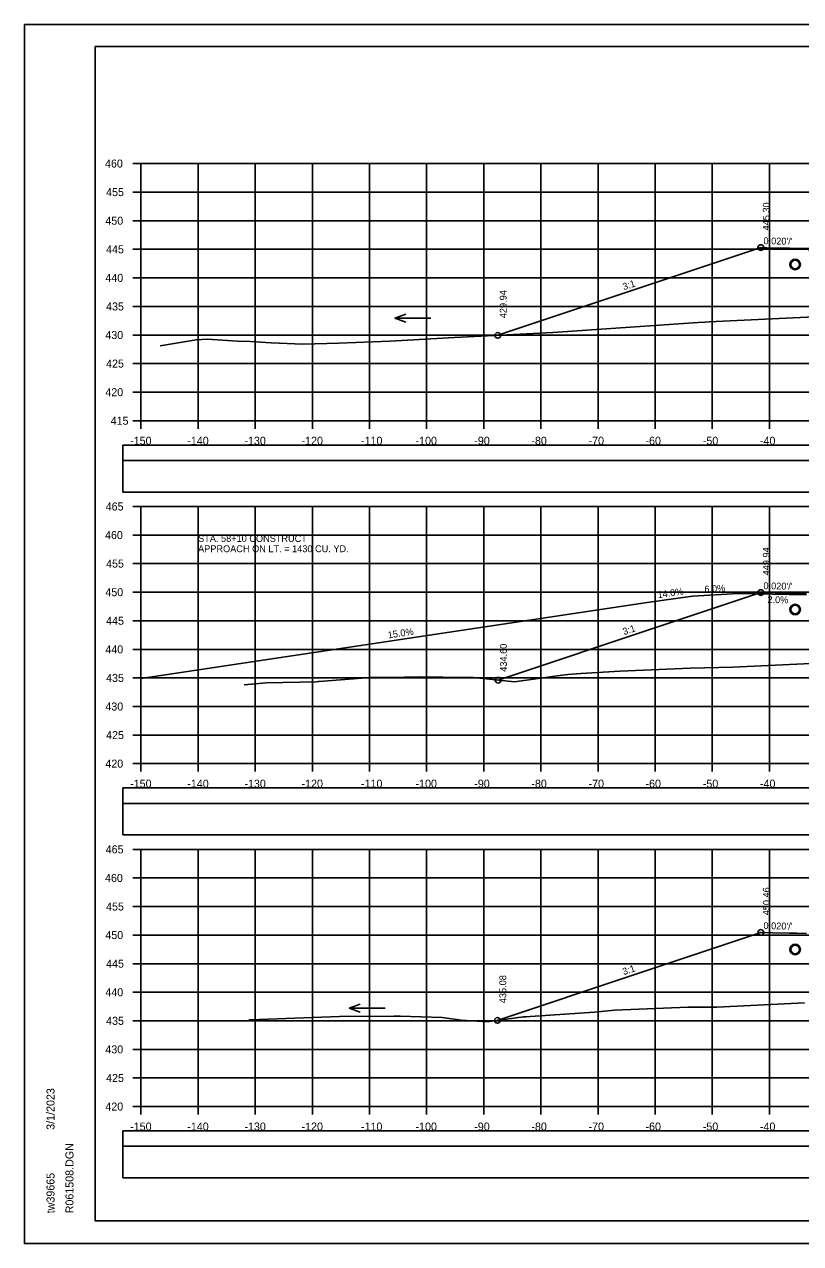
# Model space of a CAD drawing. Extents: x 1371057 to 1372761, y 380005 to 390517.
# Drawn here: x 1371390.5 to 1371526.3, y 384271.8 to 384485.2 of the extents above; entities that cross this region are included whole.
import ezdxf

# ---------------------------------------------------------------- set-up
doc = ezdxf.new("R2010")
doc.units = 0
for name, color, linetype in [('R_Axis', 7, 'Continuous'), ('R_Axis Annot', 7, 'Continuous'), ('R_Border', 7, 'Continuous'), ('R_Detour', 7, 'Continuous'), ('R_Dimension', 7, 'Continuous'), ('R_Drive', 7, 'Continuous'), ('R_Exist Surface', 7, 'Continuous'), ('R_Fin Surface', 7, 'Continuous'), ('R_Grid', 7, 'Continuous'), ('R_No Plot', 7, 'Continuous'), ('R_Water', 7, 'Continuous'), ('R_Water Annot', 7, 'Continuous'), ('R_Xsect Elev', 7, 'Continuous'), ('R_Xsect Slope', 7, 'Continuous')]:
    doc.layers.add(name, color=color, linetype=linetype)

msp = doc.modelspace()

# ---------------------------------------------------------------- linework, layer by layer
at = {"layer": 'R_Axis'}
for p, q in [((1371409.47, 384460.82), (1371410.87, 384460.82)), ((1371410.87, 384415.82), (1371410.87, 384460.82)), ((1371409.47, 384455.82), (1371410.87, 384455.82)), ((1371409.47, 384450.82), (1371410.87, 384450.82)), ((1371409.47, 384445.82), (1371410.87, 384445.82)), ((1371409.47, 384440.82), (1371410.87, 384440.82)), ((1371409.47, 384435.82), (1371410.87, 384435.82)), ((1371409.47, 384430.82), (1371410.87, 384430.82)), ((1371409.47, 384425.82), (1371410.87, 384425.82)), ((1371409.47, 384420.82), (1371410.87, 384420.82)), ((1371409.47, 384415.82), (1371410.87, 384415.82)), ((1371410.87, 384415.82), (1371710.87, 384415.82)), ((1371410.87, 384414.42), (1371410.87, 384415.82)), ((1371420.87, 384414.42), (1371420.87, 384415.82)), ((1371430.87, 384414.42), (1371430.87, 384415.82)), ((1371440.87, 384414.42), (1371440.87, 384415.82)), ((1371450.87, 384414.42), (1371450.87, 384415.82)), ((1371460.87, 384414.42), (1371460.87, 384415.82)), ((1371470.87, 384414.42), (1371470.87, 384415.82)), ((1371480.87, 384414.42), (1371480.87, 384415.82)), ((1371490.87, 384414.42), (1371490.87, 384415.82)), ((1371500.87, 384414.42), (1371500.87, 384415.82)), ((1371510.87, 384414.42), (1371510.87, 384415.82)), ((1371520.87, 384414.42), (1371520.87, 384415.82)), ((1371409.47, 384400.82), (1371410.87, 384400.82)), ((1371410.87, 384355.82), (1371410.87, 384400.82)), ((1371409.47, 384395.82), (1371410.87, 384395.82)), ((1371409.47, 384390.82), (1371410.87, 384390.82)), ((1371409.47, 384385.82), (1371410.87, 384385.82)), ((1371409.47, 384380.82), (1371410.87, 384380.82)), ((1371409.47, 384375.82), (1371410.87, 384375.82)), ((1371409.47, 384370.82), (1371410.87, 384370.82)), ((1371409.47, 384365.82), (1371410.87, 384365.82)), ((1371409.47, 384360.82), (1371410.87, 384360.82)), ((1371409.47, 384355.82), (1371410.87, 384355.82)), ((1371410.87, 384355.82), (1371710.87, 384355.82)), ((1371410.87, 384354.42), (1371410.87, 384355.82)), ((1371420.87, 384354.42), (1371420.87, 384355.82)), ((1371430.87, 384354.42), (1371430.87, 384355.82)), ((1371440.87, 384354.42), (1371440.87, 384355.82)), ((1371450.87, 384354.42), (1371450.87, 384355.82)), ((1371460.87, 384354.42), (1371460.87, 384355.82)), ((1371470.87, 384354.42), (1371470.87, 384355.82)), ((1371480.87, 384354.42), (1371480.87, 384355.82)), ((1371490.87, 384354.42), (1371490.87, 384355.82)), ((1371500.87, 384354.42), (1371500.87, 384355.82)), ((1371510.87, 384354.42), (1371510.87, 384355.82)), ((1371520.87, 384354.42), (1371520.87, 384355.82)), ((1371409.47, 384340.82), (1371410.87, 384340.82)), ((1371410.87, 384295.82), (1371410.87, 384340.82)), ((1371409.47, 384335.82), (1371410.87, 384335.82)), ((1371409.47, 384330.82), (1371410.87, 384330.82)), ((1371409.47, 384325.82), (1371410.87, 384325.82)), ((1371409.47, 384320.82), (1371410.87, 384320.82)), ((1371409.47, 384315.82), (1371410.87, 384315.82)), ((1371409.47, 384310.82), (1371410.87, 384310.82)), ((1371409.47, 384305.82), (1371410.87, 384305.82)), ((1371409.47, 384300.82), (1371410.87, 384300.82)), ((1371409.47, 384295.82), (1371410.87, 384295.82)), ((1371410.87, 384295.82), (1371710.87, 384295.82)), ((1371410.87, 384294.42), (1371410.87, 384295.82)), ((1371420.87, 384294.42), (1371420.87, 384295.82)), ((1371430.87, 384294.42), (1371430.87, 384295.82)), ((1371440.87, 384294.42), (1371440.87, 384295.82)), ((1371450.87, 384294.42), (1371450.87, 384295.82)), ((1371460.87, 384294.42), (1371460.87, 384295.82)), ((1371470.87, 384294.42), (1371470.87, 384295.82)), ((1371480.87, 384294.42), (1371480.87, 384295.82)), ((1371490.87, 384294.42), (1371490.87, 384295.82)), ((1371500.87, 384294.42), (1371500.87, 384295.82)), ((1371510.87, 384294.42), (1371510.87, 384295.82)), ((1371520.87, 384294.42), (1371520.87, 384295.82))]:
    msp.add_line(p, q, dxfattribs=at)
at = {"layer": 'R_Border'}
for p, q in [((1371402.87, 384481.28), (1371719.05, 384481.28)), ((1371402.87, 384275.82), (1371402.87, 384481.28)), ((1371402.87, 384275.82), (1371402.87, 384275.82)), ((1371719.05, 384275.82), (1371402.87, 384275.82))]:
    msp.add_line(p, q, dxfattribs=at)
at = {"layer": 'R_Detour'}
for points in [[(1371407.72, 384408.87), (1371714.03, 384408.87), (1371714.03, 384411.57), (1371407.72, 384411.57)], [(1371407.72, 384348.87), (1371714.03, 384348.87), (1371714.03, 384351.57), (1371407.72, 384351.57)], [(1371407.72, 384288.87), (1371714.03, 384288.87), (1371714.03, 384291.57), (1371407.72, 384291.57)]]:
    msp.add_lwpolyline(points, close=True, dxfattribs=at)
at = {"layer": 'R_Dimension'}
for points in [[(1371407.72, 384403.34), (1371714.03, 384403.34), (1371714.03, 384408.87), (1371407.72, 384408.87)], [(1371407.72, 384343.34), (1371714.03, 384343.34), (1371714.03, 384348.87), (1371407.72, 384348.87)], [(1371407.72, 384283.34), (1371714.03, 384283.34), (1371714.03, 384288.87), (1371407.72, 384288.87)]]:
    msp.add_lwpolyline(points, close=True, dxfattribs=at)
at = {"layer": 'R_Drive'}
for p, q in [((1371515.38, 384385.59), (1371507.39, 384385.11)), ((1371527.38, 384385.35), (1371515.38, 384385.59)), ((1371499.47, 384384), (1371410.87, 384370.71)), ((1371507.39, 384385.11), (1371499.47, 384384))]:
    msp.add_line(p, q, dxfattribs=at)
at = {"layer": 'R_Exist Surface'}
for points in [[(1371414.23, 384428.92), (1371420.55, 384429.97), (1371422.53, 384430.07), (1371427.79, 384429.77), (1371430.02, 384429.68), (1371433.64, 384429.48), (1371439.21, 384429.21), (1371445.52, 384429.4), (1371454.41, 384429.75), (1371465.72, 384430.36), (1371482.97, 384431.28), (1371508.37, 384433), (1371509.58, 384433.07), (1371510.32, 384433.11), (1371533.59, 384434.26)], [(1371428.95, 384369.6), (1371432.78, 384369.94), (1371441.58, 384370.16), (1371441.87, 384370.17), (1371442.09, 384370.19), (1371451.03, 384370.92), (1371454.31, 384370.91), (1371459.59, 384371), (1371467.84, 384370.9), (1371468.87, 384370.89), (1371469.1, 384370.87), (1371476.24, 384370.12), (1371483.33, 384371.13), (1371485.56, 384371.44), (1371487.89, 384371.59), (1371494.68, 384372.03), (1371507.08, 384372.5), (1371514.45, 384372.71), (1371531.86, 384373.52)], [(1371429.78, 384311.01), (1371431.54, 384311.03), (1371445.61, 384311.56), (1371455.11, 384311.61), (1371455.83, 384311.63), (1371456.21, 384311.62), (1371463.61, 384311.41), (1371466.93, 384310.96), (1371470.65, 384310.69), (1371471.87, 384310.72), (1371477.82, 384311.51), (1371478.23, 384311.54), (1371479, 384311.58), (1371490.24, 384312.33), (1371493.74, 384312.67), (1371506.59, 384313.19), (1371511.64, 384313.21), (1371527, 384313.98)]]:
    msp.add_lwpolyline(points, dxfattribs=at)
at = {"layer": 'R_Fin Surface'}
for points in [[(1371473.32, 384430.76), (1371473.32, 384430.77), (1371519.37, 384446.12), (1371520.44, 384446.09), (1371524.37, 384446.02), (1371527.37, 384445.96), (1371527.87, 384445.96), (1371527.88, 384445.46), (1371528.87, 384445.48), (1371552.77, 384445.95), (1371560.87, 384446.12), (1371569.95, 384445.93), (1371592.87, 384445.48), (1371592.87, 384445.48), (1371593.87, 384445.46), (1371593.87, 384445.96), (1371594.03, 384445.96), (1371594.37, 384445.96), (1371595.87, 384445.99), (1371597.37, 384446.02), (1371602.37, 384446.12), (1371606.11, 384444.87), (1371607.53, 384444.4)], [(1371473.37, 384370.42), (1371473.37, 384370.43), (1371502.23, 384380.05), (1371519.37, 384385.76), (1371519.37, 384385.76), (1371519.37, 384385.76), (1371524.37, 384385.66), (1371527.37, 384385.6)], [(1371473.25, 384310.9), (1371473.27, 384310.91), (1371473.59, 384311.01), (1371497.12, 384318.86), (1371519.37, 384326.27), (1371519.37, 384326.28), (1371519.39, 384326.27), (1371521.4, 384326.23), (1371524.37, 384326.18), (1371525.69, 384326.15), (1371527.37, 384326.12)]]:
    msp.add_lwpolyline(points, dxfattribs=at)
at = {"layer": 'R_Grid'}
for p, q in [((1371410.87, 384460.82), (1371710.87, 384460.82)), ((1371410.87, 384415.82), (1371410.87, 384460.82)), ((1371420.87, 384415.82), (1371420.87, 384460.82)), ((1371430.87, 384415.82), (1371430.87, 384460.82)), ((1371440.87, 384415.82), (1371440.87, 384460.82)), ((1371450.87, 384415.82), (1371450.87, 384460.82)), ((1371460.87, 384415.82), (1371460.87, 384460.82)), ((1371470.87, 384415.82), (1371470.87, 384460.82)), ((1371480.87, 384415.82), (1371480.87, 384460.82)), ((1371490.87, 384415.82), (1371490.87, 384460.82)), ((1371500.87, 384415.82), (1371500.87, 384460.82)), ((1371510.87, 384415.82), (1371510.87, 384460.82)), ((1371520.87, 384415.82), (1371520.87, 384460.82)), ((1371410.87, 384455.82), (1371710.87, 384455.82)), ((1371410.87, 384450.82), (1371710.87, 384450.82)), ((1371410.87, 384445.82), (1371710.87, 384445.82)), ((1371410.87, 384440.82), (1371710.87, 384440.82)), ((1371410.87, 384435.82), (1371710.87, 384435.82)), ((1371410.87, 384430.82), (1371710.87, 384430.82)), ((1371410.87, 384425.82), (1371710.87, 384425.82)), ((1371410.87, 384420.82), (1371710.87, 384420.82)), ((1371410.87, 384415.82), (1371710.87, 384415.82)), ((1371410.87, 384400.82), (1371710.87, 384400.82)), ((1371410.87, 384355.82), (1371410.87, 384400.82)), ((1371420.87, 384355.82), (1371420.87, 384400.82)), ((1371430.87, 384355.82), (1371430.87, 384400.82)), ((1371440.87, 384355.82), (1371440.87, 384400.82)), ((1371450.87, 384355.82), (1371450.87, 384400.82)), ((1371460.87, 384355.82), (1371460.87, 384400.82)), ((1371470.87, 384355.82), (1371470.87, 384400.82)), ((1371480.87, 384355.82), (1371480.87, 384400.82)), ((1371490.87, 384355.82), (1371490.87, 384400.82)), ((1371500.87, 384355.82), (1371500.87, 384400.82)), ((1371510.87, 384355.82), (1371510.87, 384400.82)), ((1371520.87, 384355.82), (1371520.87, 384400.82)), ((1371410.87, 384395.82), (1371710.87, 384395.82)), ((1371410.87, 384390.82), (1371710.87, 384390.82)), ((1371410.87, 384385.82), (1371710.87, 384385.82)), ((1371410.87, 384380.82), (1371710.87, 384380.82)), ((1371410.87, 384375.82), (1371710.87, 384375.82)), ((1371410.87, 384370.82), (1371710.87, 384370.82)), ((1371410.87, 384365.82), (1371710.87, 384365.82)), ((1371410.87, 384360.82), (1371710.87, 384360.82)), ((1371410.87, 384355.82), (1371710.87, 384355.82)), ((1371410.87, 384340.82), (1371710.87, 384340.82)), ((1371410.87, 384295.82), (1371410.87, 384340.82)), ((1371420.87, 384295.82), (1371420.87, 384340.82)), ((1371430.87, 384295.82), (1371430.87, 384340.82)), ((1371440.87, 384295.82), (1371440.87, 384340.82)), ((1371450.87, 384295.82), (1371450.87, 384340.82)), ((1371460.87, 384295.82), (1371460.87, 384340.82)), ((1371470.87, 384295.82), (1371470.87, 384340.82)), ((1371480.87, 384295.82), (1371480.87, 384340.82)), ((1371490.87, 384295.82), (1371490.87, 384340.82)), ((1371500.87, 384295.82), (1371500.87, 384340.82)), ((1371510.87, 384295.82), (1371510.87, 384340.82)), ((1371520.87, 384295.82), (1371520.87, 384340.82)), ((1371410.87, 384335.82), (1371710.87, 384335.82)), ((1371410.87, 384330.82), (1371710.87, 384330.82)), ((1371410.87, 384325.82), (1371710.87, 384325.82)), ((1371410.87, 384320.82), (1371710.87, 384320.82)), ((1371410.87, 384315.82), (1371710.87, 384315.82)), ((1371410.87, 384310.82), (1371710.87, 384310.82)), ((1371410.87, 384305.82), (1371710.87, 384305.82)), ((1371410.87, 384300.82), (1371710.87, 384300.82)), ((1371410.87, 384295.82), (1371710.87, 384295.82))]:
    msp.add_line(p, q, dxfattribs=at)
at = {"layer": 'R_No Plot'}
for p, q in [((1371390.47, 384485.17), (1371723.8, 384485.17)), ((1371390.47, 384271.84), (1371723.8, 384271.84))]:
    msp.add_line(p, q, dxfattribs=at)
for points in [[(1371390.46, 384485.17), (1371723.8, 384485.17), (1371723.8, 384271.84), (1371390.46, 384271.84)], [(1371636.79, 384481.28), (1371656.41, 384481.28), (1371656.41, 384471.4), (1371672.52, 384471.4), (1371695.72, 384471.4), (1371695.84, 384443.24), (1371719.05, 384443.24), (1371719.05, 384275.82), (1371402.87, 384275.82), (1371402.87, 384481.28)]]:
    msp.add_lwpolyline(points, close=True, dxfattribs=at)
for centre, radius in [((1371519.37, 384446.12), 0.5), ((1371525.37, 384443.16), 0.917), ((1371473.32, 384430.76), 0.5), ((1371519.37, 384385.76), 0.5), ((1371525.37, 384382.79), 0.917), ((1371473.37, 384370.42), 0.5), ((1371519.37, 384326.28), 0.5), ((1371525.37, 384323.31), 0.917), ((1371473.25, 384310.9), 0.5)]:
    msp.add_circle(centre, radius, dxfattribs=at)
at = {"layer": 'R_Water'}
for centre in [(1371525.37, 384443.16), (1371525.37, 384382.79), (1371525.37, 384323.31)]:
    msp.add_circle(centre, 0.75, dxfattribs=at)
at = {"layer": 'R_Water Annot'}
for p, q in [((1371455.31, 384433.77), (1371457.23, 384434.47)), ((1371461.59, 384433.77), (1371455.31, 384433.77)), ((1371455.31, 384433.77), (1371457.23, 384433.07)), ((1371447.34, 384313.05), (1371449.26, 384313.75)), ((1371453.62, 384313.05), (1371447.34, 384313.05)), ((1371447.34, 384313.05), (1371449.26, 384312.35))]:
    msp.add_line(p, q, dxfattribs=at)

# ---------------------------------------------------------------- texts
at = {"layer": 'R_Axis Annot'}
for s, p in [('460', (1371404.58, 384460.12)), ('455', (1371404.77, 384455.12)), ('450', (1371404.64, 384450.12)), ('445', (1371404.77, 384445.12)), ('440', (1371404.64, 384440.12)), ('435', (1371404.77, 384435.12)), ('430', (1371404.64, 384430.12)), ('425', (1371404.77, 384425.12)), ('420', (1371404.64, 384420.12)), ('415', (1371405.56, 384415.12)), ('-150', (1371408.98, 384411.62)), ('-140', (1371418.98, 384411.62)), ('-130', (1371428.98, 384411.62)), ('-120', (1371438.98, 384411.62)), ('-110', (1371449.38, 384411.62)), ('-100', (1371458.93, 384411.62)), ('-90', (1371469.21, 384411.62)), ('-80', (1371479.21, 384411.62)), ('-70', (1371489.21, 384411.62)), ('-60', (1371499.18, 384411.62)), ('-50', (1371509.21, 384411.62)), ('-40', (1371519.21, 384411.62)), ('465', (1371404.7, 384400.12)), ('460', (1371404.58, 384395.12)), ('455', (1371404.77, 384390.12)), ('450', (1371404.64, 384385.12)), ('445', (1371404.77, 384380.12)), ('440', (1371404.64, 384375.12)), ('435', (1371404.77, 384370.12)), ('430', (1371404.64, 384365.12)), ('425', (1371404.77, 384360.12)), ('420', (1371404.64, 384355.12)), ('-150', (1371408.98, 384351.62)), ('-140', (1371418.98, 384351.62)), ('-130', (1371428.98, 384351.62)), ('-120', (1371438.98, 384351.62)), ('-110', (1371449.38, 384351.62)), ('-100', (1371458.93, 384351.62)), ('-90', (1371469.21, 384351.62)), ('-80', (1371479.21, 384351.62)), ('-70', (1371489.21, 384351.62)), ('-60', (1371499.18, 384351.62)), ('-50', (1371509.21, 384351.62)), ('-40', (1371519.21, 384351.62)), ('465', (1371404.7, 384340.12)), ('460', (1371404.58, 384335.12)), ('455', (1371404.77, 384330.12)), ('450', (1371404.64, 384325.12)), ('445', (1371404.77, 384320.12)), ('440', (1371404.64, 384315.12)), ('435', (1371404.77, 384310.12)), ('430', (1371404.64, 384305.12)), ('425', (1371404.77, 384300.12)), ('420', (1371404.64, 384295.12)), ('-150', (1371408.98, 384291.62)), ('-140', (1371418.98, 384291.62)), ('-130', (1371428.98, 384291.62)), ('-120', (1371438.98, 384291.62)), ('-110', (1371449.38, 384291.62)), ('-100', (1371458.93, 384291.62)), ('-90', (1371469.21, 384291.62)), ('-80', (1371479.21, 384291.62)), ('-70', (1371489.21, 384291.62)), ('-60', (1371499.18, 384291.62)), ('-50', (1371509.21, 384291.62)), ('-40', (1371519.21, 384291.62))]:
    msp.add_text(s, height=1.4, dxfattribs=at).set_placement(p)
at = {"layer": 'R_Border'}
for s, p in [('3/1/2023', (1371395.74, 384291.75)), ('R061508.DGN', (1371399.06, 384277.14)), ('tw39665', (1371395.74, 384277.14))]:
    msp.add_text(s, height=1.4, rotation=90, dxfattribs=at).set_placement(p)
at = {"layer": 'R_Water Annot'}
for s, p in [('APPROACH ON LT. = 1430 CU. YD.', (1371420.87, 384392.82)), ('STA. 58+10 CONSTRUCT', (1371420.87, 384394.62))]:
    msp.add_text(s, height=1.2, dxfattribs=at).set_placement(p)
at = {"layer": 'R_Xsect Elev'}
for s, rotation, p in [('445.30', 90, (1371520.92, 384449.12)), ('429.94', 90, (1371474.87, 384433.76)), ('449.94', 90, (1371520.92, 384388.76)), ('14.0%', 7.9696, (1371501.37, 384384.77)), ('6.0%', 3.4336, (1371509.52, 384385.74)), ('2.0%', 358.8542, (1371520.51, 384383.94)), ('15.0%', 8.5308, (1371454.16, 384377.71)), ('434.60', 90, (1371474.92, 384371.9)), ('450.46', 90, (1371520.92, 384329.28)), ('435.08', 90, (1371474.8, 384313.9))]:
    msp.add_text(s, height=1.2, rotation=rotation, dxfattribs=at).set_placement(p)
at = {"layer": 'R_Xsect Slope'}
for s, rotation, p in [("0.020'/'", 358.8543, (1371519.82, 384446.71)), ('3:1', 18.4347, (1371495.4, 384438.65)), ("0.020'/'", 358.8543, (1371519.82, 384386.35)), ('3:1', 18.435, (1371495.42, 384378.3)), ("0.020'/'", 358.8543, (1371519.82, 384326.87)), ('3:1', 18.4352, (1371495.37, 384318.8))]:
    msp.add_text(s, height=1.2, rotation=rotation, dxfattribs=at).set_placement(p)

doc.saveas('drawing.dxf')
